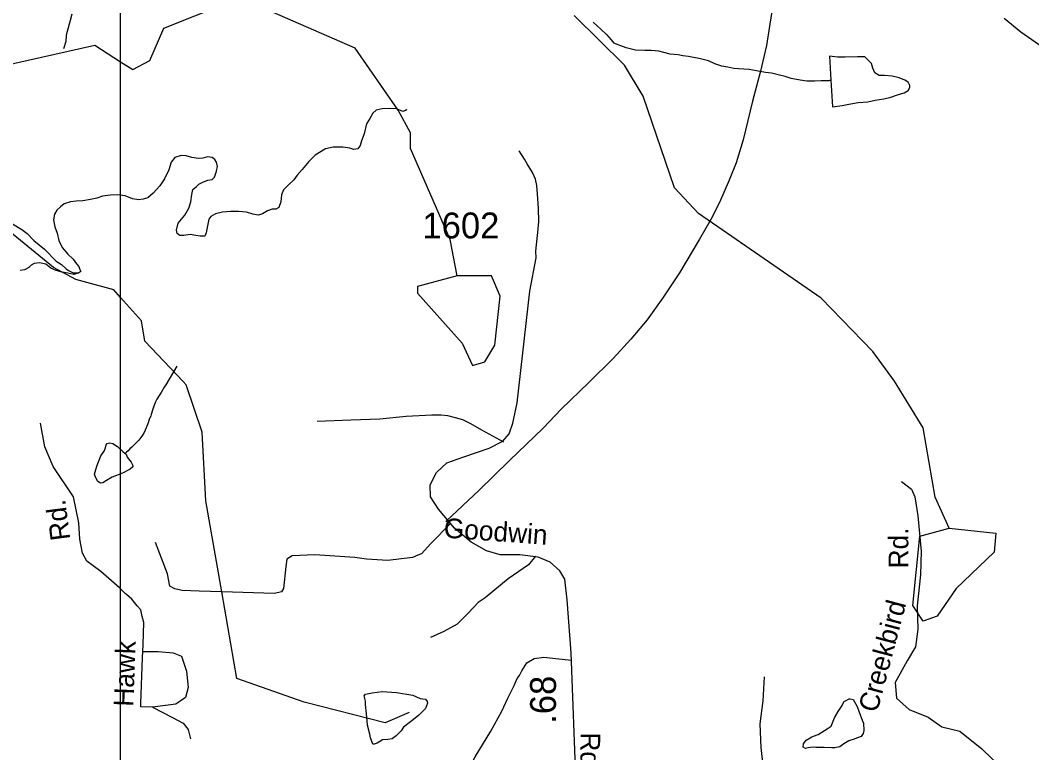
# Model space of a CAD drawing. Extents: x 2001466 to 2224147, y 644118 to 847247.
# Drawn here: x 2019988 to 2024874, y 726170 to 729712 of the extents above; entities that cross this region are included whole.
import ezdxf

# ---------------------------------------------------------------- set-up
doc = ezdxf.new("R2010")
doc.units = 0
for name, color, linetype in [('Exist Hydrographic Creek Single Shore', 7, 'Continuous'), ('Exist Hydrographic Misc Water Feature', 7, 'Continuous'), ('Exist Railroad Mainline', 7, 'Continuous'), ('Exist Road Non-System Type 51', 7, 'Continuous'), ('Exist Road Non-System Type 51 Label', 7, 'Continuous'), ('Exist Road Secondary Mileage Hundredths English Label', 7, 'Continuous'), ('Exist Road Secondary Type 51 Attributed', 7, 'Continuous'), ('Exist Road Secondary Type 51 Label', 7, 'Continuous'), ('Exist Road Secondary Type 51 Number Label', 7, 'Continuous'), ('Map Preparation Inset Cut Line', 7, 'Continuous')]:
    doc.layers.add(name, color=color, linetype=linetype)

msp = doc.modelspace()

# ---------------------------------------------------------------- linework, layer by layer
at = {"layer": 'Exist Hydrographic Creek Single Shore'}
for points in [[(2020472.9, 729511.2), (2020531.4, 729473.4), (2020614.4, 729517.5), (2020681.4, 729673.7), (2020981.4, 729792.3), (2021189.4, 729784.8)], [(2017565.5, 729323.8), (2017706.3, 729357.1), (2017765.4, 729415), (2017923.5, 729405.2), (2018248.3, 729441.2), (2018398.4, 729382.4), (2018773.4, 729407.5), (2019114.4, 729482.5), (2019181.3, 729464.8), (2019323.4, 729258.5), (2019631.4, 729281.7), (2019806.3, 729389.7), (2019898.4, 729489.5), (2020348.4, 729591.9), (2020472.9, 729511.2)]]:
    msp.add_lwpolyline(points, dxfattribs=at)
at = {"layer": 'Exist Hydrographic Misc Water Feature'}
msp.add_line((2020790.3, 727948.9), (2020775.4, 727964.8), dxfattribs=at)
for points in [[(2021814.4, 729276.5), (2021606.4, 729576.1), (2021206.4, 729751.6), (2021189.4, 729784.8)], [(2020237.5, 729741), (2020229.5, 729710.8), (2020219.7, 729674.9), (2020209.8, 729639), (2020207.8, 729608.7), (2020196.7, 729573.7)], [(2024211, 727966.9), (2024106.4, 728110.9), (2023856.3, 728368.7), (2023264.3, 728777.8), (2023148.4, 728901.6), (2022997.3, 729344.3), (2022906.3, 729493.8), (2022664.3, 729734.9)], [(2022756, 729701.9), (2022775, 729684.3), (2022793.3, 729668.4), (2022819.3, 729642.4), (2022843.3, 729616.5), (2022856, 729600.6)], [(2023904, 729422.5), (2023893.4, 729419.5), (2023857.5, 729419.4), (2023825.5, 729417.6), (2023787.6, 729417.5), (2023755.4, 729421.5), (2023711.5, 729429.8), (2023683.4, 729439.4), (2023649.4, 729447.5), (2023617.4, 729455.5), (2023587.7, 729459.4), (2023545.4, 729467.6), (2023509.5, 729473.3), (2023457.4, 729476.8), (2023435.5, 729478.9), (2023405.6, 729485.2), (2023377.5, 729489.1), (2023343.4, 729501.3), (2023313.5, 729515), (2023273.5, 729524.9), (2023215.5, 729536.7), (2023189.4, 729540.5), (2023165.5, 729545.1), (2023127.5, 729548.3), (2023097.6, 729556.3), (2023073.4, 729562.5), (2023055.5, 729564.5), (2023035.4, 729565), (2023005.5, 729564.8), (2022959.6, 729566.5), (2022915.5, 729578.1), (2022856, 729600.6)], [(2023904, 729422.5), (2023911.6, 729293.6), (2023957.8, 729300), (2023989.8, 729306), (2024035.7, 729314.1), (2024081.8, 729318.1), (2024117.5, 729325.6), (2024159.5, 729332.1), (2024193.4, 729340.4), (2024225.6, 729350.4), (2024257.6, 729360.4), (2024277.7, 729372.3), (2024285.6, 729386), (2024285.4, 729395.9), (2024277.4, 729412.5), (2024261.5, 729421.9), (2024233.4, 729433.9), (2024199.5, 729442), (2024163.4, 729444.4), (2024137.4, 729444.1), (2024115.5, 729457.6), (2024107.3, 729479.9), (2024099.5, 729502.3), (2024083.3, 729518.2), (2024067.3, 729534.1), (2024033.2, 729535.6), (2023973.4, 729533.5), (2023935.4, 729533.5), (2023897.3, 729537.5), (2023904, 729422.5)], [(2020257.4, 728458.5), (2020148.3, 728516.5), (2019740.5, 728849.7), (2019673.4, 728864.2), (2019565.4, 729007.4), (2019489.5, 729048.4), (2019356.4, 728998.6), (2019115.5, 729000.2), (2018490.5, 728773.5), (2018407.4, 728771.9), (2018182.5, 728891.3), (2017923.5, 728972), (2017756.4, 729155.9), (2017565.5, 729271.3), (2017565.5, 729323.8)], [(2021853.5, 729281.5), (2021850, 729275), (2021836.1, 729271.2), (2021806, 729283.3), (2021772.3, 729284.8), (2021736, 729283.1), (2021708.1, 729277.1), (2021692.2, 729262.7), (2021676.2, 729236.7), (2021660.2, 729210.8), (2021650.1, 729162.6), (2021636.4, 729128.4), (2021630.4, 729106.4), (2021618.3, 729090.3), (2021600.3, 729086.5), (2021580.4, 729092.6), (2021546.2, 729098.3), (2021500.4, 729098.4), (2021462.3, 729090.2), (2021412.5, 729060), (2021382.5, 729028.6), (2021350.7, 728989.9), (2021326.5, 728962.5), (2021310.5, 728939.8), (2021284.7, 728915.8), (2021260.7, 728891.6), (2021250.9, 728868.1), (2021246.8, 728833.7), (2021236.9, 728806), (2021222.8, 728798.1), (2021204.9, 728797.7), (2021182.8, 728789.9), (2021158.8, 728775.6), (2021138.9, 728769.5), (2021111, 728774.1), (2021081.1, 728783.8), (2021043, 728787.8), (2021003.2, 728787.8), (2020965, 728783.7), (2020931, 728775.3), (2020909.1, 728763.5), (2020899, 728749.8), (2020889.2, 728701.5), (2020887.1, 728683.5), (2020879.9, 728667.2), (2020857.2, 728667.8), (2020837.1, 728671.4), (2020809, 728675.2), (2020779.1, 728670.9), (2020759.2, 728671.4), (2020747.1, 728681.4), (2020743.2, 728697.1), (2020751.2, 728731.4), (2020783.2, 728769.3), (2020803, 728803.4), (2020812.9, 728833.5), (2020816.8, 728869.5), (2020822.7, 728893.2), (2020838.9, 728907.6), (2020850.8, 728919.7), (2020872.8, 728929.9), (2020894.9, 728939.3), (2020914.8, 728941.4), (2020926.7, 728953.4), (2020936.7, 728981.9), (2020940.6, 729004), (2020936.5, 729025.4), (2020928.5, 729037.9), (2020914.6, 729048), (2020892.4, 729051.8), (2020870.7, 729045.6), (2020848.6, 729043.6), (2020816.6, 729047.5), (2020790.5, 729055.5), (2020766.3, 729057.6), (2020735.8, 729048.4), (2020716.7, 729025.8), (2020706.7, 728989.1), (2020684.7, 728945.2), (2020662.8, 728911.2), (2020630.8, 728875), (2020605, 728853.3), (2020582.8, 728847.3), (2020560.9, 728842.8), (2020530.9, 728849.1), (2020494.9, 728863), (2020458.8, 728867), (2020424.7, 728866.9), (2020384.9, 728861.1), (2020358.9, 728851), (2020326.9, 728845.1), (2020290.8, 728838.5), (2020259, 728836.6), (2020230.9, 728833.1), (2020201, 728824.7), (2020183, 728810.3), (2020164.9, 728794.3), (2020153.2, 728774.8), (2020149.1, 728746.2), (2020155.1, 728712.5)], [(2022098.4, 728476.7), (2022064.3, 728651.3), (2021873.4, 729091.6), (2021873.4, 729167.1), (2021814.4, 729276.5)], [(2019951.1, 728728), (2019995.3, 728700), (2020021.2, 728680.7), (2020053.2, 728646.4), (2020105.5, 728604.3), (2020161.2, 728546.6), (2020187.5, 728530.4), (2020209.4, 728510.3), (2020221.5, 728502.7), (2020243.5, 728490.7), (2020259.7, 728490.4), (2020271.5, 728490.9)], [(2020155.1, 728712.5), (2020167.4, 728682.6), (2020175.2, 728646.4), (2020191.4, 728612.4), (2020217.4, 728580.7), (2020243.3, 728556.4), (2020259.5, 728534.8), (2020271.6, 728520.6), (2020275.4, 728506.5), (2020281.6, 728496.6), (2020271.5, 728490.9)], [(2020271.5, 728490.9), (2020247.6, 728482.5), (2020217.4, 728488.8), (2020191.6, 728494.3), (2020161.4, 728502.3), (2020135.6, 728512.7), (2020111.6, 728532), (2020081.7, 728538.4), (2020055.4, 728536.4), (2020041.7, 728528.5), (2020029.4, 728516.4), (2020009.5, 728504.6), (2019987.6, 728502.6)], [(2020472.9, 728372), (2020440.3, 728408.8), (2020257.4, 728458.5)], [(2022098.4, 728476.7), (2021906.4, 728424.8), (2021906.4, 728392), (2022123.4, 728151.4), (2022173.4, 728042.1), (2022232.5, 728060.6), (2022281.3, 728141.6), (2022306.3, 728377.3), (2022265.3, 728476.6), (2022098.4, 728476.7)], [(2020775.4, 727964.8), (2020590.4, 728159.7), (2020573.4, 728258.5), (2020472.9, 728372)], [(2020745.2, 728039.4), (2020691.3, 727949.5), (2020683.3, 727937.5), (2020669.4, 727911.5), (2020659.3, 727897.4), (2020647.4, 727879.4), (2020641.5, 727867.4), (2020639.4, 727861.4), (2020633.5, 727845.4), (2020627.3, 727827.4), (2020621.4, 727805.5), (2020619.3, 727799.5), (2020611.3, 727781.5), (2020605.4, 727761.4), (2020591.4, 727729.4), (2020585.5, 727715.4), (2020575.4, 727701.4), (2020561.5, 727681.4), (2020545.5, 727665.5), (2020527.5, 727647.4), (2020517.4, 727639.4), (2020509.4, 727629.4), (2020501.4, 727623.4), (2020495.5, 727617.4)], [(2024475.3, 727256.9), (2024408.3, 727406), (2024350.4, 727741.7), (2024211, 727966.9)], [(2020961.4, 726948.2), (2020884.4, 727389.2), (2020867.4, 727720.9), (2020790.3, 727948.9)], [(2020495.5, 727617.4), (2020499.6, 727613.4), (2020505.5, 727599.4), (2020523.6, 727575.4), (2020531.6, 727559.4), (2020531.6, 727553.4), (2020519.5, 727541.4), (2020481.5, 727521.4), (2020431.7, 727503.4), (2020405.7, 727487.3), (2020387.6, 727475.3), (2020375.7, 727473.3), (2020363.6, 727481.3), (2020351.5, 727503.3), (2020347.6, 727517.3), (2020357.5, 727555.3), (2020377.6, 727605.3), (2020393.6, 727629.3), (2020399.5, 727645.3), (2020403.4, 727659.3), (2020407.5, 727665.3), (2020421.4, 727669.3), (2020435.6, 727665.3), (2020457.5, 727651.4), (2020483.6, 727627.4), (2020495.5, 727617.4)], [(2024475.3, 727256.9), (2024700.3, 727232.6), (2024692.3, 727140.9), (2024508.3, 726964.2), (2024417.3, 726831.6), (2024350.2, 726806.6), (2024300.4, 726883.1), (2024333.4, 727217.1), (2024475.3, 727256.9)], [(2021867.3, 726365.2), (2021751.4, 726315), (2021359.3, 726414.8), (2021034.3, 726529.8), (2020961.4, 726948.2)], [(2021664.1, 726324.2), (2021660.2, 726358.2), (2021655.9, 726404.2), (2021655.9, 726420.2), (2021649.9, 726446.2), (2021655.9, 726454.2), (2021688, 726460.2), (2021736, 726466.2), (2021806, 726462.3), (2021883.9, 726448.3), (2021920, 726432.3), (2021946, 726430.3), (2021954, 726418.4), (2021956.1, 726410.3), (2021946, 726384.4), (2021912.2, 726350.4), (2021874, 726320.3), (2021840, 726294.3), (2021828.1, 726276.3), (2021804.1, 726252.3), (2021784, 726238.3), (2021764.1, 726234.3), (2021738.1, 726232.2), (2021712, 726216.3), (2021698.1, 726212.3), (2021692.2, 726212.3), (2021680.1, 726242.2), (2021676.2, 726260.2), (2021666.1, 726304.2), (2021664.1, 726324.2)], [(2024015.8, 726235.6), (2023989.8, 726227.6), (2023965.8, 726213.5), (2023947.7, 726199.5), (2023923.7, 726193.5), (2023907.7, 726193.5), (2023871.9, 726195.5), (2023851.8, 726195.5), (2023831.9, 726195.5), (2023819.8, 726197.5), (2023803.8, 726195.4), (2023793.7, 726193.5), (2023781.8, 726191.5), (2023769.7, 726197.5), (2023771.8, 726213.5), (2023783.9, 726231.5), (2023811.8, 726247.5), (2023819.8, 726251.5), (2023841.7, 726259.5), (2023859.8, 726269.5), (2023885.8, 726285.5), (2023905.9, 726299.6), (2023921.9, 726339.5), (2023939.7, 726369.6), (2023957.8, 726399.5), (2023967.6, 726419.6), (2023973.8, 726421.6), (2023991.6, 726431.6), (2023997.8, 726431.6), (2024011.7, 726427.6), (2024031.6, 726393.6), (2024039.6, 726371.6), (2024045.7, 726353.6), (2024055.6, 726327.6), (2024061.7, 726313.6), (2024063.8, 726277.6), (2024059.9, 726263.6), (2024049.8, 726249.6), (2024027.9, 726241.6), (2024015.8, 726235.6)]]:
    msp.add_lwpolyline(points, dxfattribs=at)
at = {"layer": 'Exist Railroad Mainline'}
msp.add_lwpolyline([(2023620.1, 729763.7), (2023607.9, 729683.7), (2023593.6, 729589.8), (2023563.2, 729465.8), (2023524.9, 729320), (2023480.5, 729134.3), (2023446.2, 729022.4), (2023412.1, 728938.5), (2023365.6, 728830.6), (2023323.6, 728748.7), (2023269.2, 728653), (2023172.9, 728491.3), (2023092.6, 728369.5), (2023016.2, 728263.7), (2022938.1, 728169.9), (2022851.8, 728076.2), (2022734.7, 727960.7), (2022601.3, 727832), (2022513.8, 727739.7), (2022352.2, 727583), (2022202.8, 727438.7), (2022047.2, 727292), (2022043.4, 727287.3)], dxfattribs=at)
at = {"layer": 'Exist Road Non-System Type 51'}
msp.add_line((2020627, 726391.7), (2020570.8, 726393.1), dxfattribs=at)
for points in [[(2022479.7, 728563.6), (2022478.2, 728595), (2022482.2, 728626.7), (2022488.8, 728684.9), (2022492.7, 728739.1), (2022491.4, 728801.2), (2022487.5, 728872.6), (2022483.5, 728913.6), (2022476.9, 728944), (2022462.4, 728975.7), (2022437.2, 729018), (2022424, 729040.5), (2022398.9, 729080.2)], [(2020496.9, 726939.6), (2020467.2, 726967.7), (2020378.1, 727046.6), (2020340.2, 727073.7), (2020309.3, 727096.9), (2020289.6, 727134.7), (2020276.5, 727203.1), (2020270.7, 727282.3), (2020245.6, 727407.8), (2020147.2, 727554.6), (2020106.6, 727650.2), (2020085.6, 727764.6)], [(2021422.8, 727774), (2021585, 727779.7), (2021724.9, 727785.4), (2021852.9, 727797), (2021976.9, 727804.9), (2022020.9, 727804.8), (2022052.8, 727800.7), (2022089, 727791.8), (2022123.8, 727781.1), (2022162.8, 727762.5), (2022216.6, 727732.4), (2022322.5, 727674.2)], [(2024244.7, 727481.8), (2024293.6, 727445.1), (2024309, 727408.3), (2024324.3, 727316.4), (2024339.6, 727144.8), (2024336.5, 727031.4), (2024321.2, 726881.3), (2024324.3, 726768), (2024312, 726682.2), (2024272.2, 726614.8), (2024214, 726510.6), (2024220.2, 726434), (2024281.4, 726378.9), (2024373.3, 726342.1), (2024440.6, 726296.1), (2024526.3, 726274.7), (2024633.5, 726188.9), (2024779.9, 726047.5), (2024812.3, 725957.5)], [(2022066.7, 727278.4), (2021971.9, 727181.5), (2021925.9, 727132.8), (2021908.9, 727125.3)], [(2020961.4, 726948.2), (2020851.9, 726951.5), (2020770.7, 726954.2), (2020735.6, 726962.3), (2020711.2, 726975.8), (2020700.4, 727035.4), (2020640.9, 727186.9)], [(2021908.9, 727125.3), (2021882.6, 727113.8), (2021763.6, 727100.3), (2021660.8, 727105.7), (2021604, 727113.8), (2021411.9, 727127.4), (2021301, 727122), (2021276.6, 727105.7), (2021271.2, 727070.5), (2021260.4, 726965), (2021249.6, 726948.8), (2021217.1, 726940.6), (2020961.4, 726948.2)], [(2022476.6, 727121.4), (2022443.1, 727079), (2022345.7, 727011.3), (2022234.8, 726919.3), (2022199.6, 726897.7), (2022153.6, 726846.2), (2022099.5, 726792.1), (2022034.6, 726756.9), (2021969.6, 726727.2)], [(2020580.3, 726659.6), (2020582.6, 726693.5), (2020584.7, 726799.5), (2020576.9, 726829.4), (2020571, 726861.6), (2020553, 726881.5), (2020527.1, 726913.7), (2020501.1, 726935.6), (2020496.9, 726939.6)], [(2020570.8, 726393.1), (2020570.2, 726410.6), (2020578.3, 726629.8), (2020580.3, 726659.6)], [(2020580.3, 726659.6), (2020654, 726659.6), (2020727.1, 726654.2), (2020767.6, 726638), (2020792, 726564.9), (2020800.1, 726486.4), (2020786.6, 726437.7), (2020740.6, 726405.2), (2020627, 726391.7)], [(2022012.2, 725607.8), (2022012.2, 725681.5), (2022023.8, 725754.8), (2022054, 725828.6), (2022072, 725880.6), (2022094.2, 725960.6), (2022106.3, 726004.5), (2022126.3, 726042.5), (2022186.5, 726150.3), (2022260.9, 726274.2), (2022315.1, 726372.1), (2022343.1, 726434.2), (2022373.4, 726495.9), (2022389.3, 726530), (2022399.4, 726544), (2022411.1, 726567.3), (2022435.4, 726605.2), (2022470.6, 726626.9), (2022516.6, 726632.3), (2022576.1, 726626.9), (2022650.8, 726617.9)], [(2023640.7, 725817.3), (2023603.8, 725923.6), (2023590.4, 725992), (2023567.2, 726195.3), (2023563.1, 726309.7), (2023577.4, 726421.9), (2023583.6, 726537.9)], [(2020627, 726391.7), (2020724.4, 726340.3), (2020775.8, 726313.2), (2020800.1, 726283.4), (2020810.9, 726237.4)]]:
    msp.add_lwpolyline(points, dxfattribs=at)
at = {"layer": 'Exist Road Secondary Type 51 Attributed'}
for points in [[(2026871.8, 727725.2), (2026770.6, 727855.2), (2026668.5, 728086.3), (2026565.1, 728333.4), (2026515.2, 728425.2), (2026457.3, 728517), (2026405.8, 728570.1), (2026346.2, 728624.9), (2026196.6, 728721.5), (2025948.4, 728868.8), (2025805.2, 728952.6), (2025629.8, 729070.1), (2025449.6, 729197.3), (2025126.6, 729434.8), (2024943.1, 729568.5), (2024820.8, 729653.8), (2024740.4, 729719.8)], [(2022674.3, 726011.5), (2022649.4, 726654), (2022630.1, 726910), (2022619.6, 727009.9), (2022593.9, 727050.1), (2022547.2, 727092), (2022489.3, 727116.1), (2022400.8, 727127.4), (2022305.8, 727127.4), (2022239.9, 727146.7), (2022165.9, 727188.6), (2022085.4, 727256.2), (2022008.2, 727348), (2021969.6, 727407.6), (2021968.7, 727465.6), (2021999.3, 727525.1), (2022049.2, 727571.8), (2022131.3, 727600.8), (2022253.6, 727642.7), (2022319.5, 727676.5), (2022350.1, 727711.9), (2022367.8, 727763.4), (2022388.7, 727861.7), (2022449.1, 728402.7), (2022479.7, 728563.6)]]:
    msp.add_lwpolyline(points, dxfattribs=at)
at = {"layer": 'Map Preparation Inset Cut Line'}
for p, q in [((2020472.9, 729511.2), (2020472.9, 732875.9)), ((2020472.9, 728372), (2020472.9, 729511.2)), ((2020472.9, 726933.7), (2020472.9, 728372)), ((2020472.9, 725344.9), (2020472.9, 726933.7))]:
    msp.add_line(p, q, dxfattribs=at)

# ---------------------------------------------------------------- texts
at = {"layer": 'Exist Road Non-System Type 51 Label'}
for s, rotation, p in [('Rd.', 97.4508, (2020230.4, 727202.8)), ('Rd.', 90, (2024278, 727061.6)), ('Creekbird', 75.1148, (2024127.2, 726360.7)), ('Hawk', 87.8797, (2020534.5, 726392.1))]:
    msp.add_text(s, height=95, rotation=rotation, dxfattribs=at).set_placement(p)
at = {"layer": 'Exist Road Secondary Mileage Hundredths English Label'}
msp.add_text('.68', height=125, rotation=90, dxfattribs=at).set_placement((2022576, 726310.5))
at = {"layer": 'Exist Road Secondary Type 51 Label'}
for s, rotation, p in [('Goodwin', 355.988, (2022031.8, 727211)), ('Rd.', 269.8629, (2022694.6, 726269.1))]:
    msp.add_text(s, height=95, rotation=rotation, dxfattribs=at).set_placement(p)
at = {"layer": 'Exist Road Secondary Type 51 Number Label'}
msp.add_text('1602', height=125, dxfattribs=at).set_placement((2021930.8, 728657.3))

doc.saveas('drawing.dxf')
